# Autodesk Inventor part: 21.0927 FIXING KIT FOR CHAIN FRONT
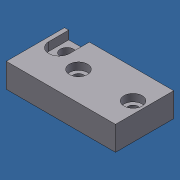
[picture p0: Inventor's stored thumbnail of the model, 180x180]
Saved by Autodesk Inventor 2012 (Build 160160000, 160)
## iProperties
Created: 2013-11
Part Number: 21.0927 FIXING KIT FOR CHAIN FRONT
Material: Aluminum-6061
Document SubType Name: Modeling
Designer: Admin
Density: 2.71 g/cm^3
Mass: 213.229 g
Surface Area: 158.04 cm^2
Volume: 78.6823 cm^3
FINISH: MILL FINISH
Author: Admin
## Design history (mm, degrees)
sketch "Sketch1"
  geometry: L1 (-45, 24)-(45, 24); L2 (45, 24)-(45, -24); L3 (45, -24)-(-45, -24); L4 (-45, -24)-(-45, 24); 3 further points
  constraints: 8 end point, 2 midpoint, 2 parallel, 1 horizontal, 1 horizontal alignment, 1 perpendicular, 1 vertical alignment
  dimensions: "d0" = 90 distance of L1.start L1.end; "d1" = 48 distance of L3.end L1.start
extrude "Extrusion1" new body sketch "Sketch1" stored distance "d2" = 20; taper "d3" = 0 deg
sketch "Sketch2"
  geometry: L1 (45, 24)-(45, -24) reference; L2 (-45, 24)-(45, 24) reference; L3 (-45, -24)-(-45, 24) reference; C1 r 4.25 at (35.5, 0); C2 r 4.25 at (-9.5, 0); C3 r 5.5 at (-33, 14); 1 further point
  constraints: 3 centre point, 2 horizontal alignment
  dimensions: "d4" = 8.5 diameter of C1; "d5" = 8.5 diameter of C2; "d6" = 9.5 distance from line of C1.centre L1; "d7" = 12 distance from line of C3.centre L3; "d8" = 10 distance from line of C3.centre L2; "d9" = 11 diameter of C3; "d21" = 45 distance of C2.centre C1.centre
extrude "Extrusion2" cut sketch "Sketch2" stored distance "d11" = 0; taper "d12" = 0 deg
sketch "Sketch3"
  geometry: C1 r 4.25 at (-9.5, 0) reference; C2 r 4.25 at (35.5, 0) reference; C3 r 7.5 at (35.5, 0); C4 r 7.5 at (-9.5, 0); 1 further point
  constraints: 2 centre point, 2 coincident
  dimensions: "d13" = 15 diameter of C3; "d14" = 15 diameter of C4
extrude "Extrusion3" cut sketch "Sketch3" distance "d15" = 6; taper "d16" = 0 deg
sketch "Sketch4"
  geometry: L1 (-45, 24)-(45, 24) reference; L2 (45, -24)-(-45, -24) reference; L3 (-41.55, 7.55)-(-41.55, 24); L4 (-24.45, 7.55)-(-24.45, 24); C1 r 5.5 at (-33, 14) reference; A1 r 8.55 centre (-33, 7.55) between (-41.55, 7.55) and (-24.45, 7.55); 1 further point
  constraints: 4 end point, 2 perpendicular, 2 point on circle, 2 point on line, 2 tangent, 1 centre point, 1 vertical alignment
  dimensions: "d17" = 8.55 radius of A1; "d20" = 25 dimension on A1 L1
extrude "Extrusion4" cut sketch "Sketch4" distance "d18" = 7; taper "d19" = 0 deg
mirror "Mirror1"
body "Solid1"
